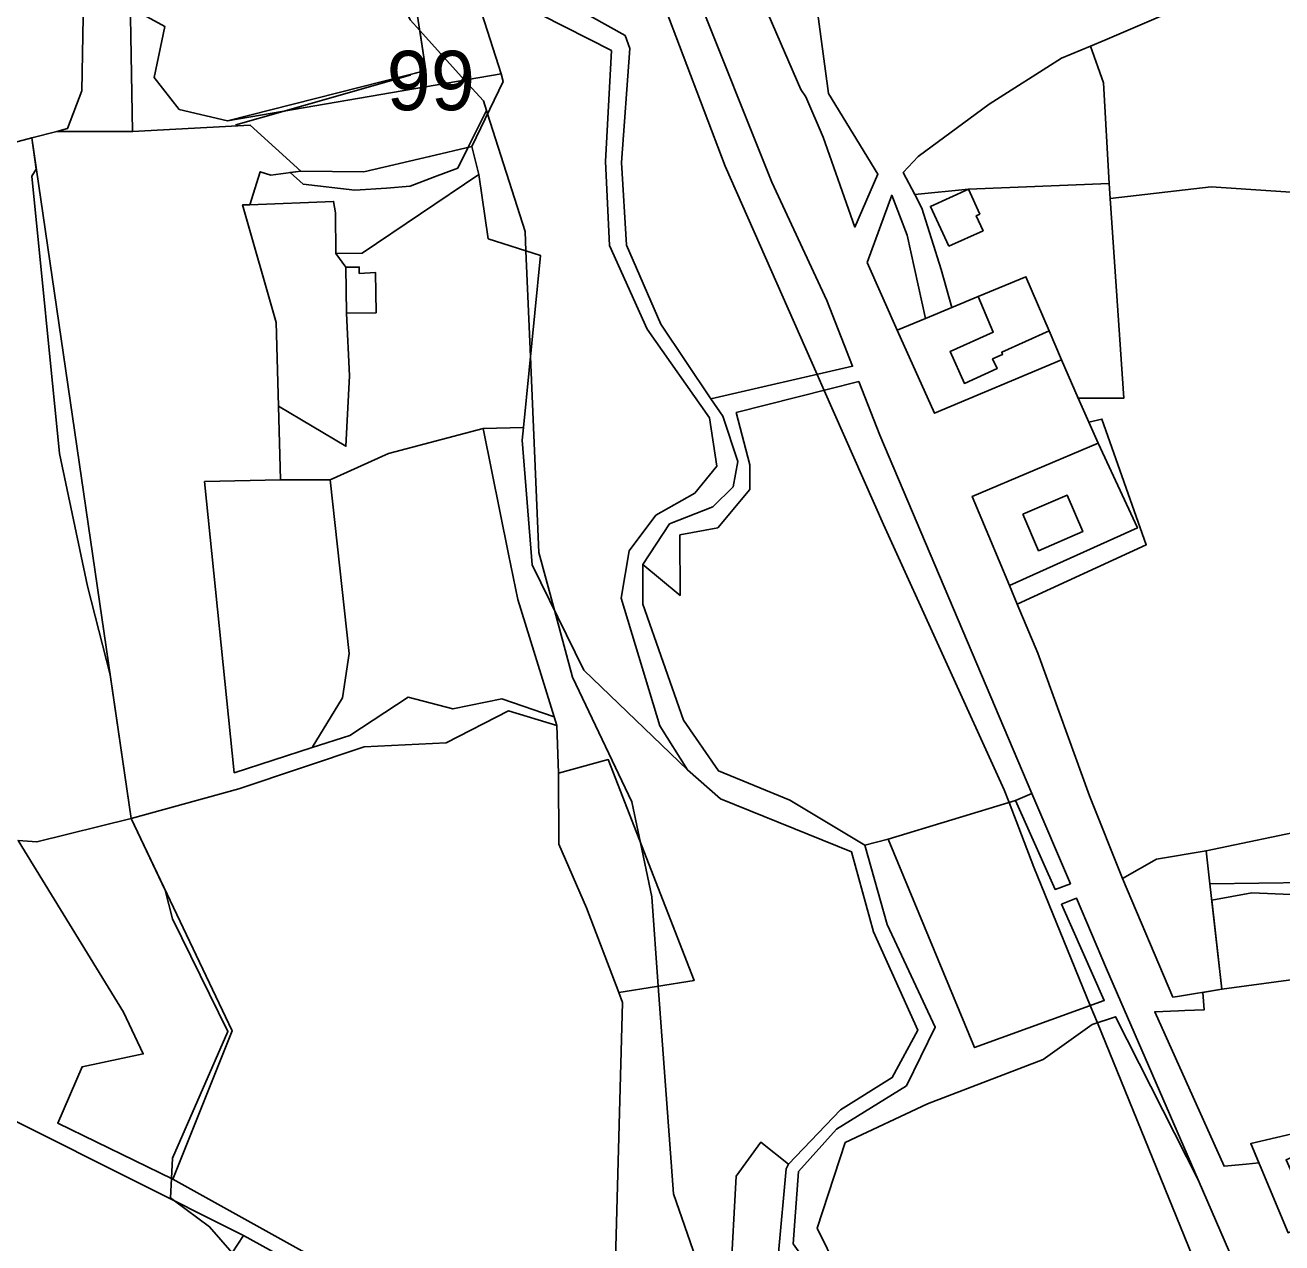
# Model space of a CAD drawing. Extents: x -477304 to -465429, y -1159113 to -1149210.
# Drawn here: x -475511.7 to -475194.4, y -1153882.9 to -1153575.4 of the extents above; entities that cross this region are included whole.
import ezdxf

# ---------------------------------------------------------------- set-up
doc = ezdxf.new("R2010")
doc.units = 0
for name, color, linetype in [('BPEJ_s', 7, 'Continuous'), ('PUPFL_s', 7, 'Continuous'), ('trav_porost_s', 7, 'Continuous'), ('voda_s', 7, 'Continuous'), ('zahrada_s', 7, 'Continuous')]:
    doc.layers.add(name, color=color, linetype=linetype)

msp = doc.modelspace()

# ---------------------------------------------------------------- linework, layer by layer
at = {"layer": 'BPEJ_s'}
for points in [[(-475408, -1153388.5), (-475389, -1153428), (-475380, -1153445), (-475381.15, -1153473.45), (-475381.37, -1153478.8), (-475381.5, -1153482), (-475376.56, -1153500.4), (-475376, -1153502.5), (-475350.87, -1153569), (-475335, -1153611), (-475311.77, -1153663.55), (-475309.99, -1153667.58), (-475295, -1153701.5), (-475264.5, -1153768.5), (-475263.28, -1153771.68), (-475257, -1153788), (-475242.78, -1153822.94), (-475241, -1153827.3), (-475211, -1153901), (-475203.65, -1153917.85), (-475190.52, -1153947.91)], [(-475412.07, -1153576.69), (-475414.5, -1153574), (-475416.5, -1153569.5), (-475422.5, -1153565.5), (-475437, -1153547.5), (-475437.36, -1153546.47), (-475438.14, -1153544.3), (-475445, -1153525), (-475444.94, -1153517.84), (-475444.89, -1153511.04), (-475444.72, -1153489.17), (-475444.56, -1153468.21), (-475444.5, -1153460.5), (-475447, -1153426), (-475448.26, -1153422.23), (-475449.74, -1153417.79)], [(-475211, -1153901), (-475241, -1153827.3), (-475242.78, -1153822.94), (-475257, -1153788), (-475263.28, -1153771.68), (-475264.5, -1153768.5), (-475295, -1153701.5), (-475309.99, -1153667.58), (-475311.77, -1153663.55), (-475335, -1153611), (-475350.87, -1153569)], [(-475414.5, -1153574), (-475412.07, -1153576.69), (-475410.51, -1153586.77), (-475414.5, -1153587.79), (-475414.5, -1153588), (-475446.67, -1153597.14), (-475458.5, -1153600.5), (-475458.2, -1153600.77), (-475454.88, -1153600.58), (-475442.1, -1153612.19), (-475444.83, -1153612.56), (-475441.5, -1153615.5), (-475428.5, -1153617), (-475420.5, -1153616.5), (-475414.5, -1153616), (-475408.35, -1153613.7), (-475402.5, -1153611.5), (-475399.86, -1153606.2), (-475395.23, -1153596.91), (-475394.97, -1153597.75), (-475385.5, -1153627.5), (-475385.29, -1153632.35), (-475384.14, -1153659.09), (-475382, -1153708.5), (-475378.05, -1153723.13), (-475373.5, -1153740), (-475358.5, -1153771.5), (-475356.35, -1153781.81), (-475353.5, -1153795.5), (-475351.85, -1153818.06), (-475348, -1153870.5), (-475339.5, -1153894.97)], [(-475339.5, -1153894.97), (-475348, -1153870.5), (-475351.85, -1153818.06), (-475353.5, -1153795.5), (-475356.35, -1153781.81), (-475358.5, -1153771.5), (-475373.5, -1153740), (-475378.05, -1153723.13), (-475382, -1153708.5), (-475384.14, -1153659.09), (-475385.29, -1153632.35), (-475385.5, -1153627.5), (-475394.97, -1153597.75), (-475395.23, -1153596.91), (-475396, -1153594.5), (-475400.76, -1153589.22), (-475412.07, -1153576.69)], [(-475459.43, -1153885.41), (-475465.15, -1153878.81), (-475474.01, -1153872.24), (-475475, -1153871.5), (-475474.76, -1153866.65), (-475474.5, -1153861.5), (-475460.5, -1153829.5), (-475474.5, -1153801), (-475476.33, -1153793.84), (-475484.97, -1153775.68), (-475490.26, -1153739.43), (-475496, -1153717), (-475503, -1153683.5), (-475510, -1153613.5), (-475508.9, -1153611.69), (-475510.04, -1153603.85), (-475528.97, -1153608.89)], [(-475459.43, -1153885.41), (-475465.15, -1153878.81), (-475474.01, -1153872.24), (-475475, -1153871.5), (-475474.76, -1153866.65), (-475474.5, -1153861.5), (-475460.5, -1153829.5), (-475474.5, -1153801), (-475476.33, -1153793.84), (-475484.97, -1153775.68), (-475490.26, -1153739.43), (-475496, -1153717), (-475503, -1153683.5), (-475510, -1153613.5), (-475508.9, -1153611.69), (-475510.04, -1153603.85), (-475528.97, -1153608.89)], [(-475163.36, -1153848.67), (-475202.25, -1153857.8), (-475200.22, -1153862.65), (-475203.46, -1153862.96), (-475209, -1153863.5), (-475226.5, -1153824.5), (-475220.5, -1153824.26), (-475218.92, -1153824.2), (-475214, -1153824), (-475214.33, -1153819.61), (-475209.54, -1153818.83), (-475212.12, -1153796.31), (-475202, -1153794.5), (-475166.5, -1153796)], [(-475166.5, -1153796), (-475202, -1153794.5), (-475212.12, -1153796.31), (-475209.54, -1153818.83), (-475214.33, -1153819.61), (-475214, -1153824), (-475218.92, -1153824.2), (-475220.5, -1153824.26), (-475226.5, -1153824.5), (-475209, -1153863.5), (-475203.46, -1153862.96), (-475200.22, -1153862.65), (-475202.25, -1153857.8), (-475163.36, -1153848.67)]]:
    msp.add_lwpolyline(points, dxfattribs=at)
msp.add_lwpolyline([(-475395.23, -1153596.91), (-475399.86, -1153606.2), (-475402.5, -1153611.5), (-475408.35, -1153613.7), (-475414.5, -1153616), (-475420.5, -1153616.5), (-475428.5, -1153617), (-475441.5, -1153615.5), (-475444.83, -1153612.56), (-475442.1, -1153612.19), (-475454.88, -1153600.58), (-475458.2, -1153600.77), (-475458.5, -1153600.5), (-475446.67, -1153597.14), (-475414.5, -1153588), (-475414.5, -1153587.79), (-475410.51, -1153586.77), (-475412.07, -1153576.69), (-475400.76, -1153589.22), (-475396, -1153594.5)], close=True, dxfattribs=at)
at = {"layer": 'PUPFL_s'}
for points in [[(-475493.46, -1153459.75), (-475492.82, -1153484.93), (-475485.96, -1153525.23), (-475485.53, -1153549.13), (-475484.58, -1153602.24), (-475503.68, -1153602.19), (-475500.98, -1153601.49), (-475497.4, -1153591.91), (-475497, -1153568.53), (-475498.83, -1153560.34), (-475509.21, -1153546.37), (-475515.54, -1153541.79), (-475521.85, -1153525.95), (-475527.95, -1153510.61), (-475534.2, -1153498.06), (-475542.48, -1153488.38), (-475552.87, -1153479.13), (-475558.66, -1153477.28), (-475550.55, -1153471.31), (-475539.7, -1153463.29), (-475500.44, -1153434.27)], [(-475432.02, -1153546.07), (-475482.52, -1153549.89), (-475482.75, -1153572.24), (-475476.45, -1153575.67), (-475479.14, -1153588.6), (-475472.8, -1153596.67), (-475460.65, -1153599.55), (-475391.53, -1153587.63), (-475391.04, -1153589.56), (-475398.91, -1153605.97), (-475409.6, -1153608.56), (-475426.22, -1153612.36), (-475442.1, -1153612.19), (-475454.88, -1153600.58), (-475484.58, -1153602.24), (-475485.53, -1153549.13), (-475482.51, -1153548.82), (-475475.33, -1153548.09), (-475433.71, -1153543.85)], [(-475364.19, -1153630.97), (-475354.65, -1153652.11), (-475338.96, -1153674.55), (-475337.11, -1153686.73), (-475342.63, -1153693.53), (-475352.47, -1153699.06), (-475359.24, -1153708.08), (-475361.24, -1153720.05), (-475351.5, -1153752.33), (-475344.51, -1153763.39), (-475370.65, -1153738.27), (-475383.66, -1153711.66), (-475386.24, -1153680.16), (-475385.92, -1153676.93), (-475381.58, -1153633.54), (-475394.79, -1153629.3), (-475397.19, -1153613.06), (-475398.91, -1153605.97), (-475391.04, -1153589.56), (-475391.53, -1153587.63), (-475399.15, -1153563.69), (-475363.7, -1153581.77), (-475365.19, -1153609.8)], [(-475369.94, -1153798.27), (-475376.97, -1153782.22), (-475377.03, -1153764.24), (-475364.5, -1153760.82), (-475342.83, -1153816.65), (-475361.82, -1153819.61)], [(-475497.35, -1153838.39), (-475481.89, -1153835.14), (-475486.87, -1153824.6), (-475513.48, -1153781.22), (-475508.72, -1153781.62), (-475484.97, -1153775.68), (-475459.46, -1153829.31), (-475474.44, -1153866.8), (-475503.48, -1153852.62)], [(-475145.68, -1153824.43), (-475163.99, -1153827.18), (-475170.15, -1153834.41), (-475174.82, -1153824.59), (-475178.99, -1153814.69), (-475209.54, -1153818.83), (-475212.6, -1153792.16), (-475163.12, -1153791.49), (-475155.68, -1153806.07)], [(-475459.43, -1153885.41), (-475475.52, -1153910.09), (-475499, -1153946), (-475561.66, -1153935.99), (-475538.16, -1153908.48), (-475593.35, -1153887.4), (-475590.76, -1153884.35), (-475548.73, -1153834.98), (-475541.07, -1153838.67), (-475456.54, -1153880.98)]]:
    msp.add_lwpolyline(points, close=True, dxfattribs=at)
msp.add_lwpolyline([(-475528.97, -1153608.89), (-475510.04, -1153603.85), (-475484.97, -1153775.68), (-475508.72, -1153781.62), (-475513.48, -1153781.22), (-475486.87, -1153824.6), (-475481.89, -1153835.14), (-475497.35, -1153838.39), (-475503.48, -1153852.62), (-475474.44, -1153866.8), (-475429.76, -1153891.65), (-475388.54, -1153904.32), (-475363.15, -1153905.58), (-475363.15, -1153909.28), (-475387.53, -1153907.46), (-475427.11, -1153897.26), (-475456.54, -1153880.98), (-475541.07, -1153838.67)], dxfattribs=at)
at = {"layer": 'trav_porost_s'}
for points in [[(-475354.65, -1153503.87), (-475346, -1153500.26), (-475341.09, -1153507.49), (-475325.58, -1153524.61), (-475319.31, -1153536.84), (-475313.9, -1153554.99), (-475308.84, -1153592.63), (-475296.39, -1153612.95), (-475302.22, -1153626.36), (-475310.19, -1153603.67), (-475314.64, -1153593.42), (-475315.88, -1153591.58), (-475324.08, -1153572.59), (-475328.15, -1153564.04)], [(-475460.65, -1153599.55), (-475472.8, -1153596.67), (-475479.14, -1153588.6), (-475476.45, -1153575.67), (-475482.75, -1153572.24), (-475482.52, -1153549.89), (-475432.02, -1153546.07), (-475422.7, -1153558.32), (-475414.26, -1153562.54), (-475410.51, -1153586.77)], [(-475177.74, -1153611.24), (-475119.33, -1153578.07), (-475119.47, -1153580.22), (-475124.5, -1153590.75), (-475151.09, -1153627.76), (-475178.33, -1153618.5), (-475212.23, -1153616.22), (-475237.76, -1153619.12), (-475238.02, -1153615.32), (-475239.41, -1153589.93), (-475242.7, -1153580.69), (-475239.09, -1153579.19), (-475212.03, -1153567.45), (-475190.2, -1153563.38), (-475177.22, -1153559.5)], [(-475323.22, -1153615.03), (-475309.33, -1153644.85), (-475302.79, -1153661.48), (-475338.61, -1153669.73), (-475351.25, -1153650.87), (-475359.92, -1153630.93), (-475361.16, -1153610.03), (-475359.02, -1153581.25), (-475360.24, -1153577.99), (-475368.96, -1153573.07), (-475342.3, -1153567.07)], [(-475268.33, -1153595.35), (-475250.01, -1153583.72), (-475242.7, -1153580.69), (-475239.41, -1153589.93), (-475238.02, -1153615.32), (-475273.55, -1153616.81), (-475287.1, -1153618.15), (-475290.02, -1153612.53), (-475286.27, -1153608.49)], [(-475403.72, -1153748.05), (-475391.34, -1153745.47), (-475378.18, -1153750.01), (-475377.51, -1153752.19), (-475389.66, -1153748.55), (-475405.37, -1153756.62), (-475426.1, -1153757.63), (-475457.75, -1153768.17), (-475484.97, -1153775.68), (-475510.04, -1153603.85), (-475503.68, -1153602.19), (-475484.58, -1153602.24), (-475454.88, -1153600.58), (-475442.1, -1153612.19), (-475449.68, -1153613.23), (-475452.37, -1153612.38), (-475455.01, -1153620.7), (-475456.81, -1153620.77), (-475448.34, -1153650.42), (-475447.75, -1153671.59), (-475447.24, -1153690.16), (-475466.4, -1153690.6), (-475458.92, -1153764.13), (-475439.28, -1153757.8), (-475429.74, -1153754.72), (-475415.04, -1153745.08)], [(-475426.58, -1153632.95), (-475397.19, -1153613.06), (-475394.79, -1153629.3), (-475381.58, -1153633.54), (-475385.92, -1153676.93), (-475396.06, -1153677.23), (-475419.95, -1153683.57), (-475434.67, -1153690.16), (-475447.24, -1153690.16), (-475447.75, -1153671.59), (-475430.73, -1153681.69), (-475429.82, -1153663.95), (-475430.59, -1153648.09), (-475423.09, -1153647.97), (-475423.25, -1153637.86), (-475427.35, -1153638.04), (-475427.37, -1153636.44), (-475430.77, -1153636.49), (-475433.28, -1153633.02)], [(-475278.47, -1153631.17), (-475269.84, -1153627.28), (-475271.58, -1153623.5), (-475270.68, -1153623.06), (-475273.55, -1153616.81), (-475238.02, -1153615.32), (-475237.76, -1153619.12), (-475234.27, -1153669.52), (-475245.8, -1153669.52), (-475250.07, -1153659.88), (-475253.19, -1153652.58), (-475259.03, -1153638.88), (-475271.07, -1153643.9), (-475277.76, -1153646.69), (-475280.39, -1153637.1), (-475285.33, -1153621.54), (-475287.1, -1153618.15), (-475273.55, -1153616.81), (-475283.16, -1153621.13)], [(-475234.27, -1153669.52), (-475237.76, -1153619.12), (-475212.23, -1153616.22), (-475178.33, -1153618.5), (-475149.26, -1153717.69), (-475143.43, -1153728.23), (-475125.7, -1153759.77), (-475158.82, -1153772.41), (-475213.55, -1153783.85), (-475226.06, -1153786), (-475234.63, -1153790.84), (-475243, -1153769.96), (-475256.01, -1153733.93), (-475261.21, -1153721.59), (-475228.64, -1153706.57), (-475239.85, -1153674.85), (-475243.11, -1153675.6), (-475245.8, -1153669.52)], [(-475299.09, -1153635.26), (-475292.9, -1153618.33), (-475289.03, -1153628.38), (-475284.35, -1153649.44), (-475291.5, -1153652.42)], [(-475336.78, -1153702.29), (-475328.73, -1153692.66), (-475328.73, -1153686.38), (-475332.17, -1153673.21), (-475301.26, -1153665.37), (-475295.94, -1153678.9), (-475257.5, -1153769.35), (-475261.64, -1153771.18), (-475293.81, -1153780.96), (-475299.68, -1153782.46), (-475318.68, -1153771.09), (-475336.69, -1153763.68), (-475345.52, -1153750.83), (-475355.74, -1153721.59), (-475355.72, -1153711.53), (-475346.36, -1153719.38), (-475346.4, -1153704.11)], [(-475240.75, -1153680.92), (-475243.11, -1153675.6), (-475239.85, -1153674.85), (-475228.64, -1153706.57), (-475261.21, -1153721.59), (-475263.19, -1153716.9), (-475230.88, -1153702.33)], [(-475378.18, -1153750.01), (-475391.34, -1153745.47), (-475403.72, -1153748.05), (-475415.04, -1153745.08), (-475429.74, -1153754.72), (-475439.28, -1153757.8), (-475431.58, -1153745.26), (-475429.88, -1153734.02), (-475434.67, -1153690.16), (-475419.95, -1153683.57), (-475396.06, -1153677.23), (-475389.65, -1153708.96), (-475387.29, -1153720.38)], [(-475434.67, -1153690.16), (-475429.88, -1153734.02), (-475431.58, -1153745.26), (-475439.28, -1153757.8), (-475458.92, -1153764.13), (-475466.4, -1153690.6), (-475447.24, -1153690.16)], [(-475405.37, -1153756.62), (-475389.66, -1153748.55), (-475377.51, -1153752.19), (-475377.03, -1153764.24), (-475376.97, -1153782.22), (-475369.94, -1153798.27), (-475361.82, -1153819.61), (-475360.91, -1153822.16), (-475363.15, -1153905.58), (-475388.54, -1153904.32), (-475429.76, -1153891.65), (-475474.44, -1153866.8), (-475459.46, -1153829.31), (-475484.97, -1153775.68), (-475457.75, -1153768.17), (-475426.1, -1153757.63)], [(-475257.5, -1153769.35), (-475247.81, -1153792.17), (-475251.68, -1153793.63), (-475261.64, -1153771.18)], [(-475212.6, -1153792.16), (-475213.55, -1153783.85), (-475158.82, -1153772.41), (-475163.12, -1153791.49)], [(-475281.86, -1153913.47), (-475286.07, -1153917.2), (-475304.69, -1153901.53), (-475317.83, -1153883.13), (-475316.44, -1153864.83), (-475306.89, -1153854.13), (-475289.22, -1153843.24), (-475281.91, -1153828.38), (-475294.04, -1153802.48), (-475299.68, -1153782.46), (-475293.81, -1153780.96), (-475271.98, -1153833.55), (-475239.24, -1153821.65), (-475250.03, -1153797.34), (-475246.27, -1153795.8), (-475238.66, -1153813.69), (-475215.58, -1153866.95), (-475236.4, -1153825.75), (-475242.32, -1153827.75), (-475254.64, -1153836.55), (-475283.88, -1153847.76), (-475304.66, -1153857.55), (-475311.76, -1153879.17), (-475306.6, -1153889.58)], [(-475221.94, -1153820.85), (-475234.63, -1153790.84), (-475226.06, -1153786), (-475213.55, -1153783.85), (-475212.6, -1153792.16), (-475209.54, -1153818.83), (-475220.72, -1153820.65)], [(-475306.6, -1153889.58), (-475311.76, -1153879.17), (-475304.66, -1153857.55), (-475283.88, -1153847.76), (-475254.64, -1153836.55), (-475242.32, -1153827.75), (-475236.4, -1153825.75), (-475215.58, -1153866.95), (-475198.64, -1153906.05), (-475195.98, -1153912.48), (-475244.74, -1153946.61), (-475231.26, -1153963.94), (-475247.12, -1153947.87), (-475273.09, -1153925.68), (-475286.07, -1153917.2), (-475281.86, -1153913.47)], [(-475202.25, -1153857.8), (-475163.36, -1153848.67), (-475155.95, -1153864.55), (-475166.06, -1153868.88), (-475169.35, -1153870.28), (-475169.5, -1153869.91), (-475171.49, -1153865.27), (-475183.98, -1153857.72), (-475191.83, -1153861.23), (-475193.34, -1153861.91), (-475189.82, -1153869.78), (-475188.31, -1153869.11), (-475184.78, -1153876.88), (-475192.84, -1153880.33)]]:
    msp.add_lwpolyline(points, close=True, dxfattribs=at)
for points in [[(-475515.54, -1153541.79), (-475509.21, -1153546.37), (-475498.83, -1153560.34), (-475497, -1153568.53), (-475497.4, -1153591.91), (-475500.98, -1153601.49), (-475503.68, -1153602.19), (-475510.04, -1153603.85), (-475528.97, -1153608.89)], [(-475363.15, -1153905.58), (-475360.91, -1153822.16), (-475361.82, -1153819.61), (-475342.83, -1153816.65), (-475364.5, -1153760.82), (-475377.03, -1153764.24), (-475377.51, -1153752.19), (-475378.18, -1153750.01), (-475387.29, -1153720.38), (-475389.65, -1153708.96), (-475396.06, -1153677.23), (-475385.92, -1153676.93), (-475386.24, -1153680.16), (-475383.66, -1153711.66), (-475370.65, -1153738.27), (-475344.51, -1153763.39), (-475336.14, -1153770.73), (-475303.09, -1153784.11), (-475297.51, -1153804.32), (-475286.33, -1153829.12), (-475292.8, -1153841.13), (-475305.82, -1153849.3), (-475318.94, -1153863.02), (-475325.98, -1153857.44), (-475332.17, -1153866.06), (-475333.58, -1153892.31)]]:
    msp.add_lwpolyline(points, dxfattribs=at)
at = {"layer": 'voda_s'}
for points in [[(-475409.69, -1153414.57), (-475403.11, -1153430.11), (-475399.41, -1153433.92), (-475389.41, -1153454.54), (-475403.26, -1153484.1), (-475407.29, -1153487.91), (-475425.71, -1153505.33), (-475426.38, -1153512.24), (-475418, -1153525.76), (-475416.1, -1153533.82), (-475412.56, -1153548.68), (-475368.96, -1153573.07), (-475360.24, -1153577.99), (-475359.02, -1153581.25), (-475361.16, -1153610.03), (-475359.92, -1153630.93), (-475351.25, -1153650.87), (-475338.61, -1153669.73), (-475335.57, -1153674.07), (-475331.77, -1153685.56)], [(-475321.48, -1153885.36), (-475319.54, -1153864.19), (-475318.94, -1153863.02), (-475305.82, -1153849.3), (-475292.8, -1153841.13), (-475286.33, -1153829.12), (-475297.51, -1153804.32), (-475303.09, -1153784.11), (-475336.14, -1153770.73), (-475344.51, -1153763.39), (-475351.5, -1153752.33), (-475361.24, -1153720.05), (-475359.24, -1153708.08), (-475352.47, -1153699.06), (-475342.63, -1153693.53), (-475337.11, -1153686.73), (-475338.96, -1153674.55), (-475354.65, -1153652.11), (-475364.19, -1153630.97), (-475365.19, -1153609.8), (-475363.7, -1153581.77), (-475399.15, -1153563.69)], [(-475331.77, -1153685.56), (-475332.96, -1153691.92), (-475338.07, -1153697.03), (-475349.01, -1153701.33), (-475355.72, -1153711.53), (-475355.74, -1153721.59), (-475345.52, -1153750.83), (-475336.69, -1153763.68), (-475318.68, -1153771.09), (-475299.68, -1153782.46), (-475294.04, -1153802.48), (-475281.91, -1153828.38), (-475289.22, -1153843.24), (-475306.89, -1153854.13), (-475316.44, -1153864.83), (-475317.83, -1153883.13)]]:
    msp.add_lwpolyline(points, dxfattribs=at)
at = {"layer": 'zahrada_s'}
for points in [[(-475448.34, -1153650.42), (-475456.81, -1153620.77), (-475455.01, -1153620.7), (-475433.85, -1153619.88), (-475433.39, -1153622.72), (-475433.28, -1153633.02), (-475430.77, -1153636.49), (-475430.59, -1153648.09), (-475429.82, -1153663.95), (-475430.73, -1153681.69), (-475447.75, -1153671.59)], [(-475291.5, -1153652.42), (-475284.35, -1153649.44), (-475277.76, -1153646.69), (-475271.07, -1153643.9), (-475267.3, -1153652.85), (-475278.18, -1153657.75), (-475274.55, -1153665.81), (-475266.32, -1153662.1), (-475267.43, -1153659.64), (-475264.92, -1153658.51), (-475265.15, -1153657.96), (-475253.19, -1153652.58), (-475250.07, -1153659.88), (-475282.14, -1153673.38)], [(-475263.19, -1153716.9), (-475268.43, -1153704.38), (-475272.6, -1153694.38), (-475240.75, -1153680.92), (-475230.88, -1153702.33)], [(-475259.8, -1153698.87), (-475255.82, -1153708.07), (-475244.68, -1153703.25), (-475248.66, -1153694.05)]]:
    msp.add_lwpolyline(points, close=True, dxfattribs=at)

# ---------------------------------------------------------------- texts
at = {"layer": 'BPEJ_s'}
msp.add_text('99', height=15, dxfattribs=at).set_placement((-475420.44, -1153596.84))

doc.saveas('drawing.dxf')
